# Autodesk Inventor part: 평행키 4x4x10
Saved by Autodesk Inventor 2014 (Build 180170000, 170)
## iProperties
Created: 2026-03
Part Number: 평행키 4x4x10
Material: 강철, 연강
Document SubType Name: Modeling
Designer: dg
Density: 7.86 g/cm^3
Appearance: 강철
Mass: 1.13784 g
Surface Area: 1.6404 cm^2
Volume: 0.144763 cm^3
Author: jhkim
Description: 키 및 해당 키홈
Creation Date: 2025-06-27
Sending System: Autodesk Inventor 2026
Preprocessor: ST-DEVELOPER v20.1
Author: dg
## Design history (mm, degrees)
node "평행키 4x4x101"
body "Solid1"
node "기준1"
